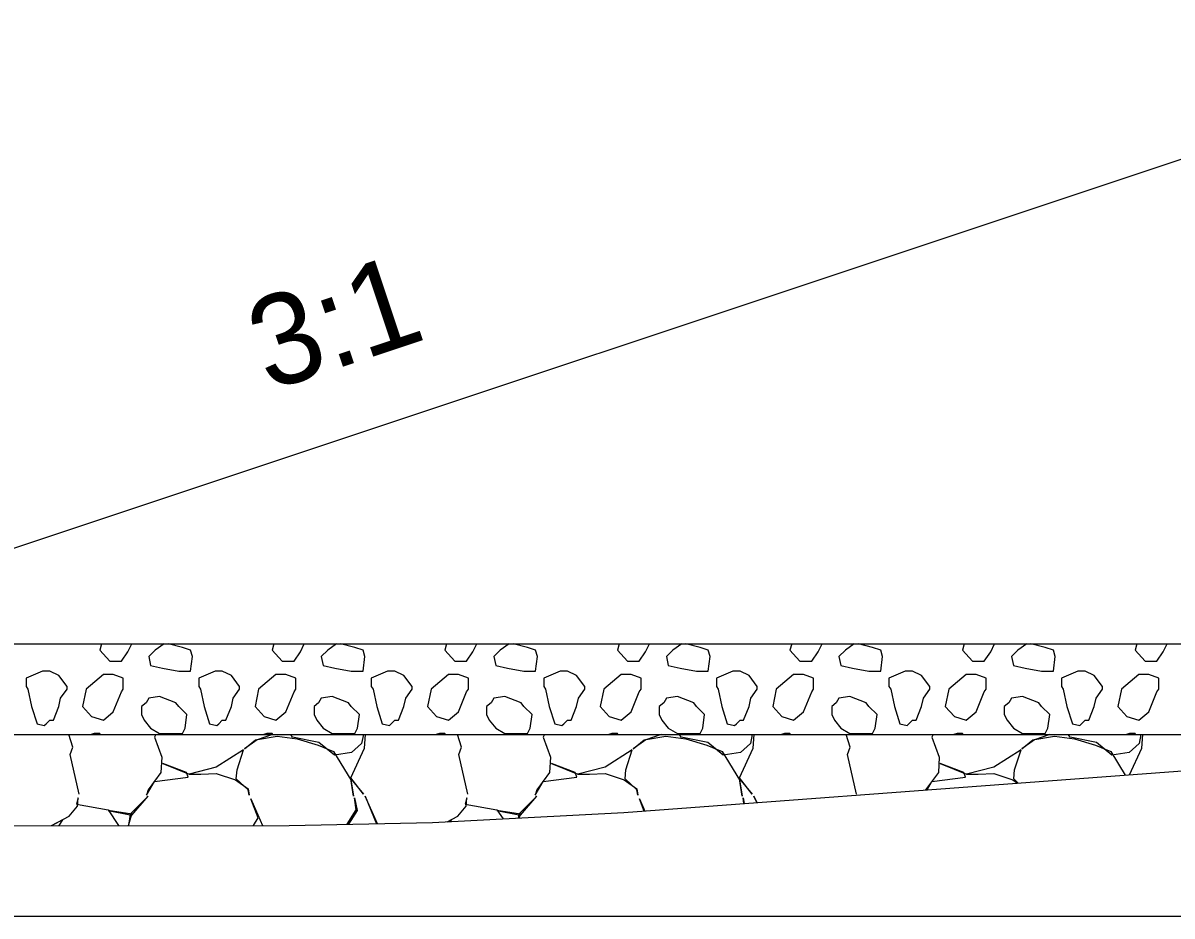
# Model space of a CAD drawing. Extents: x -26 to 4781, y -31 to 24738.
# Drawn here: x 2254.93 to 2267.58, y 9000 to 9009.84 of the extents above; entities that cross this region are included whole.
import ezdxf

# ---------------------------------------------------------------- set-up
doc = ezdxf.new("R2010")
doc.units = 0
for name, color, linetype in [('DESIGN - SHEET - Light Grid', 7, 'Continuous'), ('DESIGN - TRANSPORTATION - Proposed Layout Patterning', 7, 'Continuous'), ('DESIGN - TYPICAL - Finished Grade and Subgrade', 7, 'Continuous'), ('DESIGN - TYPICAL - Finished Grade Slopes Text', 7, 'Continuous'), ('GEOTECHNICAL – SCRATCH – Level 1', 7, 'Continuous'), ('SURVEY - GROUND - Top of Ground', 7, 'Continuous')]:
    doc.layers.add(name, color=color, linetype=linetype)

msp = doc.modelspace()

# ---------------------------------------------------------------- linework, layer by layer
at = {"layer": 'DESIGN - SHEET - Light Grid'}
msp.add_line((2000, 9000), (2300, 9000), dxfattribs=at)
at = {"layer": 'DESIGN - TRANSPORTATION - Proposed Layout Patterning'}
for p, q in [((2255.818, 9002.659), (2255.628, 9002.499)), ((2257.718, 9002.659), (2257.528, 9002.499)), ((2259.618, 9002.659), (2259.428, 9002.499)), ((2261.518, 9002.659), (2261.328, 9002.499)), ((2263.418, 9002.659), (2263.228, 9002.499)), ((2265.318, 9002.659), (2265.128, 9002.499)), ((2267.218, 9002.659), (2267.028, 9002.499)), ((2254.968, 9002.529), (2254.988, 9002.499)), ((2256.868, 9002.529), (2256.888, 9002.499)), ((2258.768, 9002.529), (2258.788, 9002.499)), ((2260.668, 9002.529), (2260.688, 9002.499)), ((2262.568, 9002.529), (2262.588, 9002.499)), ((2264.468, 9002.529), (2264.488, 9002.499)), ((2266.368, 9002.529), (2266.388, 9002.499)), ((2255.718, 9002.009), (2255.684, 9002)), ((2257.618, 9002.009), (2257.584, 9002)), ((2259.518, 9002.009), (2259.484, 9002)), ((2261.418, 9002.009), (2261.384, 9002)), ((2263.318, 9002.009), (2263.284, 9002)), ((2265.218, 9002.009), (2265.184, 9002)), ((2267.118, 9002.009), (2267.084, 9002))]:
    msp.add_line(p, q, dxfattribs=at)
for points in [[(2255.797, 9003), (2255.778, 9002.929), (2255.888, 9002.809), (2256.018, 9002.809), (2256.088, 9002.909), (2256.131, 9003)], [(2256.486, 9003), (2256.388, 9002.929), (2256.318, 9002.859), (2256.338, 9002.759), (2256.468, 9002.729), (2256.648, 9002.699), (2256.778, 9002.699), (2256.798, 9002.859), (2256.778, 9002.929)], [(2256.778, 9002.929), (2256.688, 9002.959), (2256.531, 9003)], [(2257.697, 9003), (2257.678, 9002.929), (2257.788, 9002.809), (2257.918, 9002.809), (2257.988, 9002.909), (2258.031, 9003)], [(2258.386, 9003), (2258.288, 9002.929), (2258.218, 9002.859), (2258.238, 9002.759), (2258.368, 9002.729), (2258.548, 9002.699), (2258.678, 9002.699), (2258.698, 9002.859), (2258.678, 9002.929)], [(2258.678, 9002.929), (2258.588, 9002.959), (2258.431, 9003)], [(2259.597, 9003), (2259.578, 9002.929), (2259.688, 9002.809), (2259.818, 9002.809), (2259.888, 9002.909), (2259.931, 9003)], [(2260.286, 9003), (2260.188, 9002.929), (2260.118, 9002.859), (2260.138, 9002.759), (2260.268, 9002.729), (2260.448, 9002.699), (2260.578, 9002.699), (2260.598, 9002.859), (2260.578, 9002.929)], [(2260.578, 9002.929), (2260.488, 9002.959), (2260.331, 9003)], [(2261.497, 9003), (2261.478, 9002.929), (2261.588, 9002.809), (2261.718, 9002.809), (2261.788, 9002.909), (2261.831, 9003)], [(2262.186, 9003), (2262.088, 9002.929), (2262.018, 9002.859), (2262.038, 9002.759), (2262.168, 9002.729), (2262.348, 9002.699), (2262.478, 9002.699), (2262.498, 9002.859), (2262.478, 9002.929)], [(2262.478, 9002.929), (2262.388, 9002.959), (2262.231, 9003)], [(2263.397, 9003), (2263.378, 9002.929), (2263.488, 9002.809), (2263.618, 9002.809), (2263.688, 9002.909), (2263.731, 9003)], [(2264.086, 9003), (2263.988, 9002.929), (2263.918, 9002.859), (2263.938, 9002.759), (2264.068, 9002.729), (2264.248, 9002.699), (2264.378, 9002.699), (2264.398, 9002.859), (2264.378, 9002.929)], [(2264.378, 9002.929), (2264.288, 9002.959), (2264.131, 9003)], [(2265.297, 9003), (2265.278, 9002.929), (2265.388, 9002.809), (2265.518, 9002.809), (2265.588, 9002.909), (2265.631, 9003)], [(2265.986, 9003), (2265.888, 9002.929), (2265.818, 9002.859), (2265.838, 9002.759), (2265.968, 9002.729), (2266.148, 9002.699), (2266.278, 9002.699), (2266.298, 9002.859), (2266.278, 9002.929)], [(2266.278, 9002.929), (2266.188, 9002.959), (2266.031, 9003)], [(2267.197, 9003), (2267.178, 9002.929), (2267.288, 9002.809), (2267.418, 9002.809), (2267.488, 9002.909), (2267.531, 9003)], [(2255.228, 9002.699), (2255.168, 9002.699), (2255.148, 9002.699), (2254.968, 9002.619), (2254.968, 9002.529)], [(2255.418, 9002.499), (2255.418, 9002.529), (2255.328, 9002.649), (2255.228, 9002.699)], [(2257.128, 9002.699), (2257.068, 9002.699), (2257.048, 9002.699), (2256.868, 9002.619), (2256.868, 9002.529)], [(2257.318, 9002.499), (2257.318, 9002.529), (2257.228, 9002.649), (2257.128, 9002.699)], [(2259.028, 9002.699), (2258.968, 9002.699), (2258.948, 9002.699), (2258.768, 9002.619), (2258.768, 9002.529)], [(2259.218, 9002.499), (2259.218, 9002.529), (2259.128, 9002.649), (2259.028, 9002.699)], [(2260.928, 9002.699), (2260.868, 9002.699), (2260.848, 9002.699), (2260.668, 9002.619), (2260.668, 9002.529)], [(2261.118, 9002.499), (2261.118, 9002.529), (2261.028, 9002.649), (2260.928, 9002.699)], [(2262.828, 9002.699), (2262.768, 9002.699), (2262.748, 9002.699), (2262.568, 9002.619), (2262.568, 9002.529)], [(2263.018, 9002.499), (2263.018, 9002.529), (2262.928, 9002.649), (2262.828, 9002.699)], [(2264.728, 9002.699), (2264.668, 9002.699), (2264.648, 9002.699), (2264.468, 9002.619), (2264.468, 9002.529)], [(2264.918, 9002.499), (2264.918, 9002.529), (2264.828, 9002.649), (2264.728, 9002.699)], [(2266.628, 9002.699), (2266.568, 9002.699), (2266.548, 9002.699), (2266.368, 9002.619), (2266.368, 9002.529)], [(2266.818, 9002.499), (2266.818, 9002.529), (2266.728, 9002.649), (2266.628, 9002.699)], [(2256.038, 9002.499), (2256.038, 9002.619), (2255.928, 9002.659), (2255.818, 9002.659)], [(2257.938, 9002.499), (2257.938, 9002.619), (2257.828, 9002.659), (2257.718, 9002.659)], [(2259.838, 9002.499), (2259.838, 9002.619), (2259.728, 9002.659), (2259.618, 9002.659)], [(2261.738, 9002.499), (2261.738, 9002.619), (2261.628, 9002.659), (2261.518, 9002.659)], [(2263.638, 9002.499), (2263.638, 9002.619), (2263.528, 9002.659), (2263.418, 9002.659)], [(2265.538, 9002.499), (2265.538, 9002.619), (2265.428, 9002.659), (2265.318, 9002.659)], [(2267.438, 9002.499), (2267.438, 9002.619), (2267.328, 9002.659), (2267.218, 9002.659)], [(2254.988, 9002.499), (2255.028, 9002.309), (2255.088, 9002.119), (2255.168, 9002.099), (2255.188, 9002.119), (2255.228, 9002.159)], [(2255.228, 9002.159), (2255.268, 9002.159), (2255.328, 9002.309), (2255.348, 9002.399), (2255.418, 9002.499)], [(2255.628, 9002.499), (2255.588, 9002.309), (2255.688, 9002.199), (2255.818, 9002.159), (2255.928, 9002.249), (2256.018, 9002.469), (2256.038, 9002.499)], [(2256.888, 9002.499), (2256.928, 9002.309), (2256.988, 9002.119), (2257.068, 9002.099), (2257.088, 9002.119), (2257.128, 9002.159)], [(2257.128, 9002.159), (2257.168, 9002.159), (2257.228, 9002.309), (2257.248, 9002.399), (2257.318, 9002.499)], [(2257.528, 9002.499), (2257.488, 9002.309), (2257.588, 9002.199), (2257.718, 9002.159), (2257.828, 9002.249), (2257.918, 9002.469), (2257.938, 9002.499)], [(2258.788, 9002.499), (2258.828, 9002.309), (2258.888, 9002.119), (2258.968, 9002.099), (2258.988, 9002.119), (2259.028, 9002.159)], [(2259.028, 9002.159), (2259.068, 9002.159), (2259.128, 9002.309), (2259.148, 9002.399), (2259.218, 9002.499)], [(2259.428, 9002.499), (2259.388, 9002.309), (2259.488, 9002.199), (2259.618, 9002.159), (2259.728, 9002.249), (2259.818, 9002.469), (2259.838, 9002.499)], [(2260.688, 9002.499), (2260.728, 9002.309), (2260.788, 9002.119), (2260.868, 9002.099), (2260.888, 9002.119), (2260.928, 9002.159)], [(2260.928, 9002.159), (2260.968, 9002.159), (2261.028, 9002.309), (2261.048, 9002.399), (2261.118, 9002.499)], [(2261.328, 9002.499), (2261.288, 9002.309), (2261.388, 9002.199), (2261.518, 9002.159), (2261.628, 9002.249), (2261.718, 9002.469), (2261.738, 9002.499)], [(2262.588, 9002.499), (2262.628, 9002.309), (2262.688, 9002.119), (2262.768, 9002.099), (2262.788, 9002.119), (2262.828, 9002.159)], [(2262.828, 9002.159), (2262.868, 9002.159), (2262.928, 9002.309), (2262.948, 9002.399), (2263.018, 9002.499)], [(2263.228, 9002.499), (2263.188, 9002.309), (2263.288, 9002.199), (2263.418, 9002.159), (2263.528, 9002.249), (2263.618, 9002.469), (2263.638, 9002.499)], [(2264.488, 9002.499), (2264.528, 9002.309), (2264.588, 9002.119), (2264.668, 9002.099), (2264.688, 9002.119), (2264.728, 9002.159)], [(2264.728, 9002.159), (2264.768, 9002.159), (2264.828, 9002.309), (2264.848, 9002.399), (2264.918, 9002.499)], [(2265.128, 9002.499), (2265.088, 9002.309), (2265.188, 9002.199), (2265.318, 9002.159), (2265.428, 9002.249), (2265.518, 9002.469), (2265.538, 9002.499)], [(2266.388, 9002.499), (2266.428, 9002.309), (2266.488, 9002.119), (2266.568, 9002.099), (2266.588, 9002.119), (2266.628, 9002.159)], [(2266.628, 9002.159), (2266.668, 9002.159), (2266.728, 9002.309), (2266.748, 9002.399), (2266.818, 9002.499)], [(2267.028, 9002.499), (2266.988, 9002.309), (2267.088, 9002.199), (2267.218, 9002.159), (2267.328, 9002.249), (2267.418, 9002.469), (2267.438, 9002.499)], [(2256.618, 9002.349), (2256.438, 9002.419), (2256.318, 9002.399), (2256.288, 9002.349), (2256.238, 9002.309), (2256.238, 9002.219), (2256.268, 9002.159), (2256.338, 9002.069), (2256.438, 9002.009), (2256.568, 9002.009), (2256.688, 9002.009), (2256.718, 9002.069), (2256.738, 9002.219), (2256.648, 9002.309), (2256.618, 9002.349)], [(2258.518, 9002.349), (2258.338, 9002.419), (2258.218, 9002.399), (2258.188, 9002.349), (2258.138, 9002.309), (2258.138, 9002.219), (2258.168, 9002.159), (2258.238, 9002.069), (2258.338, 9002.009), (2258.468, 9002.009), (2258.588, 9002.009), (2258.618, 9002.069), (2258.638, 9002.219), (2258.548, 9002.309), (2258.518, 9002.349)], [(2260.418, 9002.349), (2260.238, 9002.419), (2260.118, 9002.399), (2260.088, 9002.349), (2260.038, 9002.309), (2260.038, 9002.219), (2260.068, 9002.159), (2260.138, 9002.069), (2260.238, 9002.009), (2260.368, 9002.009), (2260.488, 9002.009), (2260.518, 9002.069), (2260.538, 9002.219), (2260.448, 9002.309), (2260.418, 9002.349)], [(2262.318, 9002.349), (2262.138, 9002.419), (2262.018, 9002.399), (2261.988, 9002.349), (2261.938, 9002.309), (2261.938, 9002.219), (2261.968, 9002.159), (2262.038, 9002.069), (2262.138, 9002.009), (2262.268, 9002.009), (2262.388, 9002.009), (2262.418, 9002.069), (2262.438, 9002.219), (2262.348, 9002.309), (2262.318, 9002.349)], [(2264.218, 9002.349), (2264.038, 9002.419), (2263.918, 9002.399), (2263.888, 9002.349), (2263.838, 9002.309), (2263.838, 9002.219), (2263.868, 9002.159), (2263.938, 9002.069), (2264.038, 9002.009), (2264.168, 9002.009), (2264.288, 9002.009), (2264.318, 9002.069), (2264.338, 9002.219), (2264.248, 9002.309), (2264.218, 9002.349)], [(2266.118, 9002.349), (2265.938, 9002.419), (2265.818, 9002.399), (2265.788, 9002.349), (2265.738, 9002.309), (2265.738, 9002.219), (2265.768, 9002.159), (2265.838, 9002.069), (2265.938, 9002.009), (2266.068, 9002.009), (2266.188, 9002.009), (2266.218, 9002.069), (2266.238, 9002.219), (2266.148, 9002.309), (2266.118, 9002.349)], [(2255.552, 9001.341), (2255.452, 9001.781), (2255.482, 9001.861), (2255.437, 9002)], [(2255.784, 9002), (2255.778, 9002.009), (2255.718, 9002.009)], [(2256.395, 9002), (2256.382, 9001.971), (2256.462, 9001.751), (2256.452, 9001.581), (2256.312, 9001.391), (2256.292, 9001.331), (2256.382, 9001.481), (2256.752, 9001.531), (2256.732, 9001.581), (2256.472, 9001.681), (2256.762, 9001.561), (2256.892, 9001.561), (2257.062, 9001.571), (2257.272, 9001.501), (2257.412, 9001.401), (2257.422, 9001.331), (2257.412, 9001.391), (2257.282, 9001.511), (2257.292, 9001.611), (2257.362, 9001.831), (2257.062, 9001.641), (2256.762, 9001.561)], [(2257.679, 9002), (2257.512, 9001.941), (2257.372, 9001.841), (2257.492, 9001.941), (2257.732, 9001.981), (2257.952, 9001.951), (2258.182, 9001.881), (2258.352, 9001.811), (2258.542, 9001.501), (2258.572, 9001.321), (2258.542, 9001.511), (2258.682, 9001.341), (2258.542, 9001.521), (2258.692, 9001.851), (2258.704, 9002)], [(2257.684, 9002), (2257.678, 9002.009), (2257.618, 9002.009)], [(2258.681, 9002), (2258.662, 9001.901), (2258.552, 9001.801), (2258.362, 9001.771), (2258.192, 9001.911), (2257.902, 9001.971), (2257.882, 9002)], [(2259.584, 9002), (2259.578, 9002.009), (2259.518, 9002.009)], [(2259.832, 9001.341), (2259.732, 9001.781), (2259.762, 9001.861), (2259.717, 9002)], [(2260.675, 9002), (2260.662, 9001.971), (2260.742, 9001.751), (2260.732, 9001.581), (2260.592, 9001.391), (2260.572, 9001.331), (2260.662, 9001.481), (2261.032, 9001.531), (2261.012, 9001.581), (2260.752, 9001.681), (2261.042, 9001.561), (2261.172, 9001.561), (2261.342, 9001.571), (2261.552, 9001.501), (2261.692, 9001.401), (2261.702, 9001.331), (2261.692, 9001.391), (2261.562, 9001.511), (2261.572, 9001.611), (2261.642, 9001.831), (2261.342, 9001.641), (2261.042, 9001.561)], [(2261.484, 9002), (2261.478, 9002.009), (2261.418, 9002.009)], [(2261.959, 9002), (2261.792, 9001.941), (2261.652, 9001.841), (2261.772, 9001.941), (2262.012, 9001.981), (2262.232, 9001.951), (2262.462, 9001.881), (2262.632, 9001.811), (2262.822, 9001.501), (2262.852, 9001.321), (2262.822, 9001.511), (2262.962, 9001.341), (2262.822, 9001.521), (2262.972, 9001.851), (2262.984, 9002)], [(2262.961, 9002), (2262.942, 9001.901), (2262.832, 9001.801), (2262.642, 9001.771), (2262.472, 9001.911), (2262.182, 9001.971), (2262.162, 9002)], [(2263.384, 9002), (2263.378, 9002.009), (2263.318, 9002.009)], [(2264.112, 9001.341), (2264.012, 9001.781), (2264.042, 9001.861), (2263.997, 9002)], [(2264.955, 9002), (2264.942, 9001.971), (2265.022, 9001.751), (2265.012, 9001.581), (2264.872, 9001.391), (2264.871, 9001.388)], [(2265.284, 9002), (2265.278, 9002.009), (2265.218, 9002.009)], [(2266.239, 9002), (2266.072, 9001.941), (2265.932, 9001.841), (2266.052, 9001.941), (2266.292, 9001.981), (2266.512, 9001.951), (2266.742, 9001.881), (2266.912, 9001.811), (2267.07, 9001.553)], [(2267.241, 9002), (2267.222, 9001.901), (2267.112, 9001.801), (2266.922, 9001.771), (2266.752, 9001.911), (2266.462, 9001.971), (2266.442, 9002)], [(2267.184, 9002), (2267.178, 9002.009), (2267.118, 9002.009)], [(2267.118, 9001.557), (2267.252, 9001.851), (2267.264, 9002)], [(2265.892, 9001.465), (2265.842, 9001.511), (2265.852, 9001.611), (2265.922, 9001.831), (2265.622, 9001.641), (2265.322, 9001.561)], [(2264.887, 9001.39), (2264.942, 9001.481), (2265.312, 9001.531), (2265.292, 9001.581), (2265.032, 9001.681), (2265.322, 9001.561), (2265.452, 9001.561), (2265.622, 9001.571), (2265.832, 9001.501), (2265.884, 9001.464)], [(2255.249, 9000.996), (2255.442, 9001.101), (2255.532, 9001.211), (2255.542, 9001.301), (2255.522, 9001.231), (2255.872, 9001.171), (2255.986, 9000.997)], [(2256.096, 9000.997), (2256.132, 9001.121), (2255.872, 9001.161), (2256.132, 9001.111), (2256.312, 9001.321), (2256.112, 9001.121), (2256.096, 9000.997)], [(2257.472, 9000.998), (2257.522, 9001.081), (2257.442, 9001.291), (2257.569, 9000.999)], [(2258.503, 9001.011), (2258.602, 9001.171), (2258.582, 9001.301), (2258.612, 9001.161), (2258.517, 9001.011)], [(2258.836, 9001.017), (2258.702, 9001.321), (2258.827, 9001.017)], [(2259.605, 9001.037), (2259.722, 9001.101), (2259.812, 9001.211), (2259.822, 9001.301), (2259.802, 9001.231), (2260.152, 9001.171), (2260.219, 9001.07)], [(2260.4, 9001.079), (2260.412, 9001.121), (2260.152, 9001.161), (2260.412, 9001.111), (2260.592, 9001.321), (2260.392, 9001.121), (2260.387, 9001.078)], [(2261.773, 9001.156), (2261.722, 9001.291), (2261.78, 9001.157)], [(2262.872, 9001.239), (2262.862, 9001.301), (2262.875, 9001.239)], [(2263.014, 9001.249), (2262.982, 9001.321), (2263.012, 9001.249)], [(2255.331, 9000.996), (2255.372, 9001.061), (2255.251, 9000.996)], [(2259.638, 9001.039), (2259.652, 9001.061), (2259.608, 9001.037)]]:
    msp.add_lwpolyline(points, dxfattribs=at)
at = {"layer": 'DESIGN - TYPICAL - Finished Grade and Subgrade'}
msp.add_line((2272.191, 9009.838), (2246.033, 9001.118), dxfattribs=at)
at = {"layer": 'GEOTECHNICAL – SCRATCH – Level 1'}
for p, q in [((2251.677, 9003), (2288.208, 9003)), ((2248.677, 9002), (2272.907, 9002))]:
    msp.add_line(p, q, dxfattribs=at)
at = {"layer": 'SURVEY - GROUND - Top of Ground'}
msp.add_lwpolyline([(2245.266, 9001.161), (2248.387, 9000.987), (2257.864, 9000.999), (2259.444, 9001.029), (2261.548, 9001.139), (2266.368, 9001.501), (2272.035, 9001.923), (2278.17, 9002.465), (2282.721, 9002.685), (2285.358, 9002.813), (2289.155, 9003.062), (2292.832, 9003.295), (2294.689, 9003.387), (2300, 9003.528), (2301.786, 9003.576), (2304.507, 9003.667), (2305.591, 9003.752), (2311.873, 9004.328), (2317.466, 9004.556), (2319.316, 9004.667), (2322.222, 9004.929), (2328.199, 9005.484), (2330.932, 9005.614), (2339.572, 9006.106)], dxfattribs=at)

# ---------------------------------------------------------------- texts
at = {"layer": 'DESIGN - TYPICAL - Finished Grade Slopes Text'}
msp.add_text('3:1', height=1, rotation=18.4349, dxfattribs=at).set_placement((2257.635, 9005.777))

doc.saveas('drawing.dxf')
